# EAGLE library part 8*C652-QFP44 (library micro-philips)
CMOS single-chip 8-bit Microcontroller
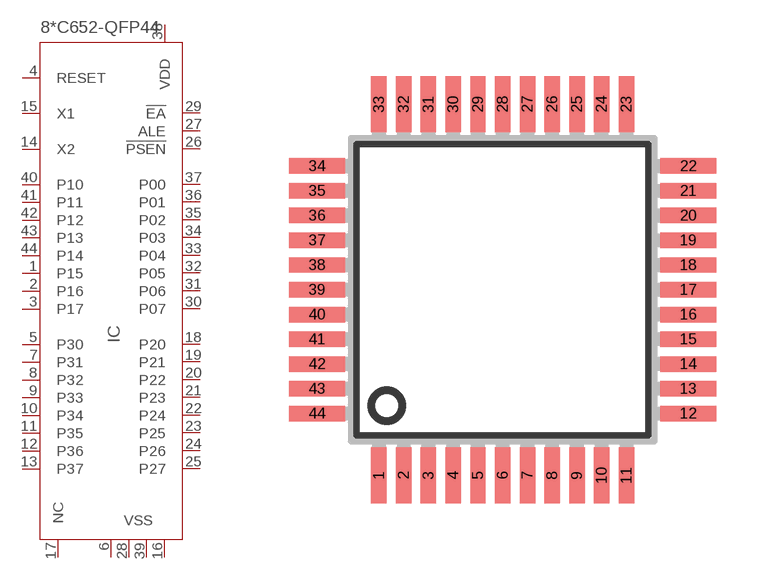
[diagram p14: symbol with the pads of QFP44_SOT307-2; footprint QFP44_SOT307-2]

Designator prefix IC

## 80C652-QFP44 (OC_FARNELL: unknown; OC_NEWARK: unknown), 83C652-QFP44 (OC_FARNELL: unknown; OC_NEWARK: unknown)  [QFP44_SOT307-2]
1  P15
2  P16
3  P17
4  RESET
5  P30
6  VSS
7  P31
8  P32
9  P33
10  P34
11  P35
12  P36
13  P37
14  X2  out
15  X1  in
16  VSS  pwr
17  NC
18  P20
19  P21
20  P22
21  P23
22  P24
23  P25
24  P26
25  P27
26  !PSEN  out
27  ALE  out
28  VSS
29  !EA  in
30  P07
31  P06
32  P05
33  P04
34  P03
35  P02
36  P01
37  P00
38  VDD  pwr
39  VSS
40  P10
41  P11
42  P12
43  P13
44  P14

## Footprint QFP44_SOT307-2 (pad centres in mm)
Plastic Quad Flat Package SOT307-2 44 leads (lead length 1.3 mm); body 10 x 10 x 1.75 mm SOT307-2 source: http://www.semiconductors.philips.com/ LQFP-MSQFP-QFP-SQFP-TQFP-REFLOW.pdf
smd 0.5 x 1.8: 1 -4,-6; 2 -3.2,-6; 3 -2.4,-6; 4 -1.6,-6; 5 -0.8,-6; 6 0,-6; 7 0.8,-6; 8 1.6,-6; 9 2.4,-6; 10 3.2,-6; 11 4,-6; 23 4,6; 24 3.2,6; 25 2.4,6; 26 1.6,6; 27 0.8,6; 28 0,6; 29 -0.8,6; 30 -1.6,6; 31 -2.4,6; 32 -3.2,6; 33 -4,6
smd 1.8 x 0.5: 12 6,-4; 13 6,-3.2; 14 6,-2.4; 15 6,-1.6; 16 6,-0.8; 17 6,0; 18 6,0.8; 19 6,1.6; 20 6,2.4; 21 6,3.2; 22 6,4; 34 -6,4; 35 -6,3.2; 36 -6,2.4; 37 -6,1.6; 38 -6,0.8; 39 -6,0; 40 -6,-0.8; 41 -6,-1.6; 42 -6,-2.4; 43 -6,-3.2; 44 -6,-4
